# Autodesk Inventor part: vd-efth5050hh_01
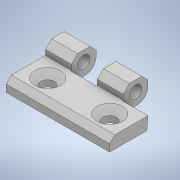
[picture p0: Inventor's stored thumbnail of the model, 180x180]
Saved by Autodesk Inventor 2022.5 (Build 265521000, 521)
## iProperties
Created: 2019-12
Part Number: vd-efth5050hh_01
Material: 一般
Document SubType Name: Modeling
Designer: ImaoCorp
Density: 1 g/cm^3
Appearance: 既定
Author: ImaoCorp
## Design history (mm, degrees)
feature "vd-efth5050hh_01"
node "ソリッド1"
